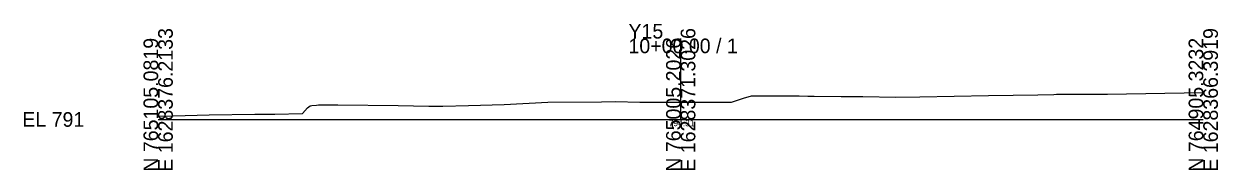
# Model space of a CAD drawing. Extents: x -26 to 203, y -10 to 2522.
# Drawn here: x -25.7 to 202.8, y -9.7 to 18.3 of the extents above; entities that cross this region are included whole.
import ezdxf

# ---------------------------------------------------------------- set-up
doc = ezdxf.new("R2010")
doc.units = 0
for name, color, linetype in [('Default', 7, 'Continuous'), ('Exist Cross Section Cell', 7, 'Continuous'), ('Exist XS Center Line Elevation Label', 7, 'Continuous'), ('Exist XS Ground Line', 7, 'Continuous')]:
    doc.layers.add(name, color=color, linetype=linetype)

msp = doc.modelspace()

# ---------------------------------------------------------------- linework, layer by layer
at = {"layer": 'Exist Cross Section Cell'}
for p, q in [((100, 0), (100, 15.48)), ((0, 0), (100, 0)), ((100, 0), (200, 0))]:
    msp.add_line(p, q, dxfattribs=at)
at = {"layer": 'Exist XS Ground Line'}
msp.add_lwpolyline([(0, 0.64), (2.86, 0.71), (9.77, 0.87), (18.51, 0.99), (22.36, 1.01), (27.6, 1.15), (28.57, 2.21), (29.06, 2.63), (29.43, 2.7), (30.29, 2.75), (30.68, 2.79), (34.38, 2.82), (45.91, 2.65), (51.82, 2.54), (54.5, 2.51), (59.41, 2.69), (66.21, 2.88), (74.6, 3.3), (84.82, 3.34), (87.55, 3.45), (92.17, 3.32), (93.6, 3.32), (100, 3.31), (109.72, 3.29), (112, 4.1), (113.53, 4.5), (114.48, 4.5), (122.65, 4.49), (124.33, 4.46), (125.54, 4.46), (130.69, 4.4), (134.84, 4.38), (141.14, 4.29), (145.78, 4.35), (158.87, 4.58), (168.37, 4.71), (171.39, 4.8), (171.92, 4.81), (181.65, 4.86), (200, 5.16)], dxfattribs=at)

# ---------------------------------------------------------------- texts
at = {"layer": 'Default'}
msp.add_text('-', height=0.0001, dxfattribs=at).set_placement((0, 0))
at = {"layer": 'Exist Cross Section Cell'}
for s, p in [('Y15', (90, 15.48)), ('10+00.00 / 1', (90, 12.68)), ('EL 791', (-26, -1.4))]:
    msp.add_text(s, height=2.8, dxfattribs=at).set_placement(p)
for s, p in [('E 1628376.2133', (2.8, -10)), ('E 1628371.3026', (102.8, -10)), ('E 1628366.3919', (202.8, -10)), ('N 765105.0819', (0, -10)), ('N 765005.2026', (100, -10)), ('N 764905.3232', (200, -10))]:
    msp.add_text(s, height=2.8, rotation=90, dxfattribs=at).set_placement(p)
at = {"layer": 'Exist XS Center Line Elevation Label'}
msp.add_text('794.31', height=1.2, dxfattribs=at).set_placement((97.71, -1.29))

doc.saveas('drawing.dxf')
